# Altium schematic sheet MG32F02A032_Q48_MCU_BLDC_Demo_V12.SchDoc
size 307 x 215 mm
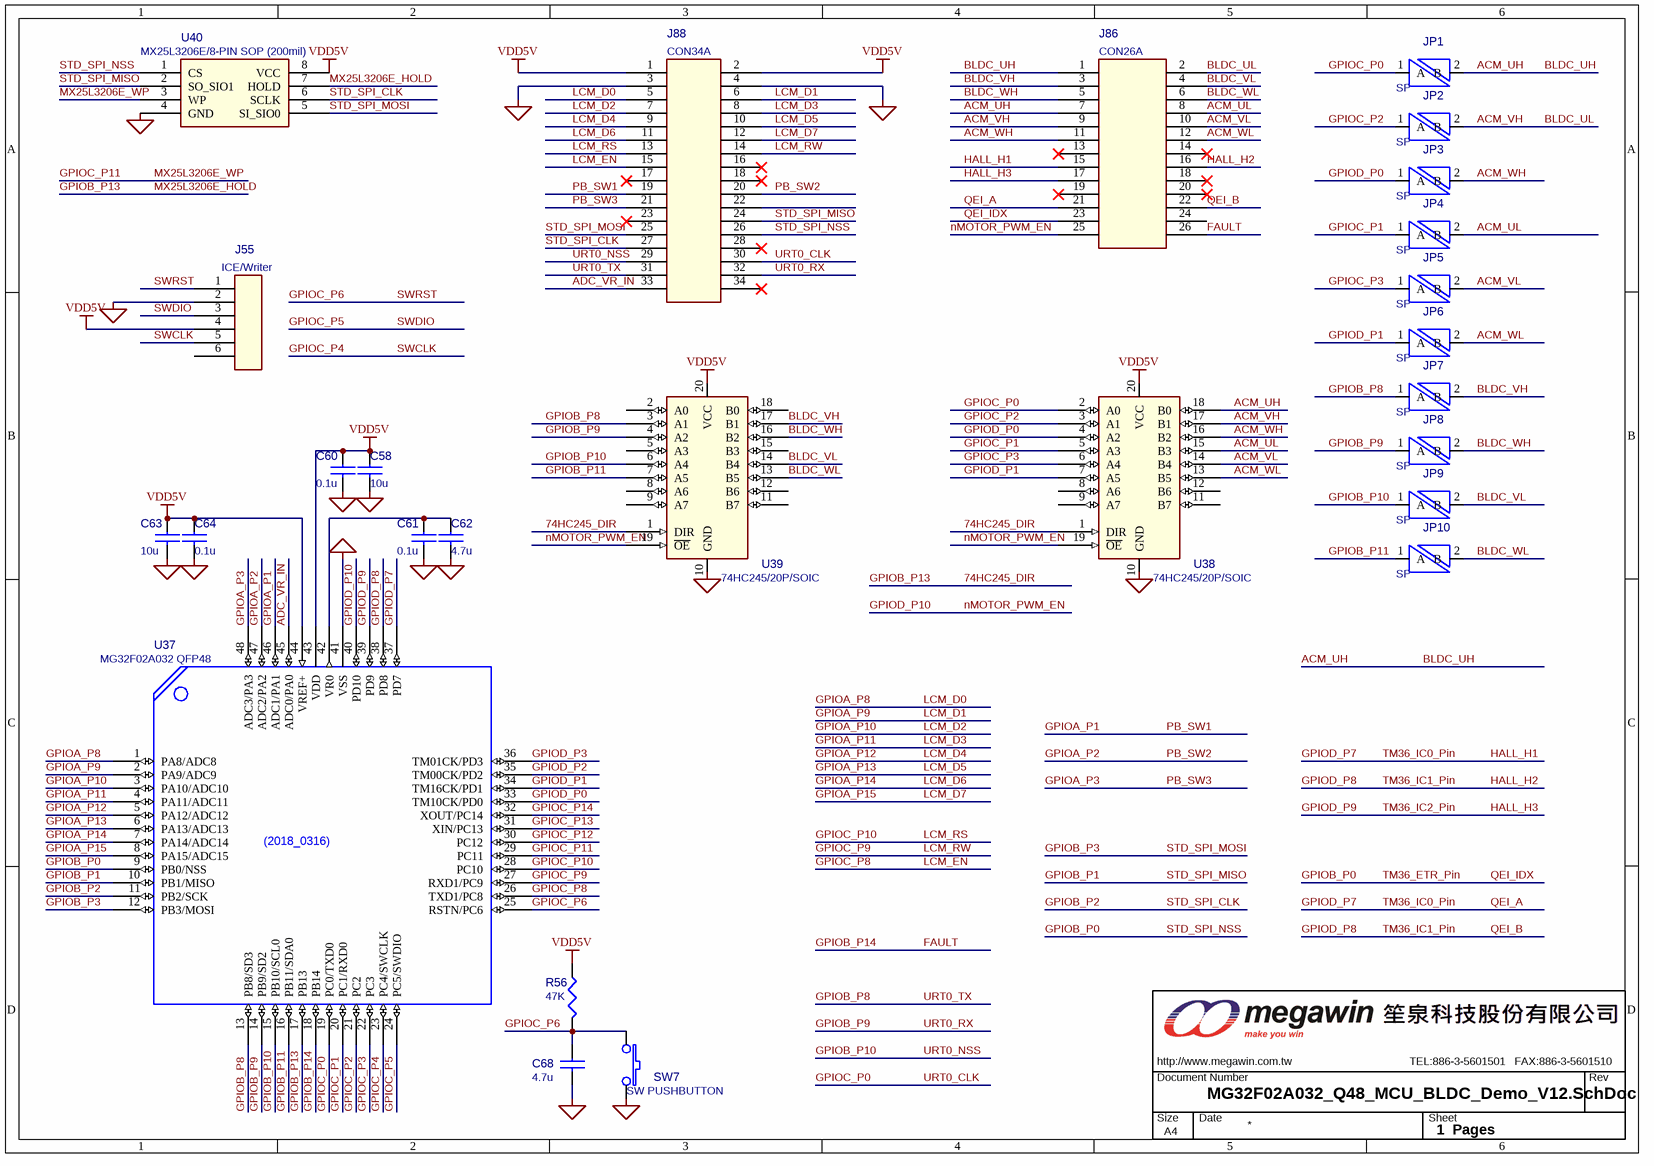
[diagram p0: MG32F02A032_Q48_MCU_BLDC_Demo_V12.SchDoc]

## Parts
C58  10u  [0805C]
C60  0.1u  [0805C]
C61  0.1u  [0805C]
C62  4.7u  [0805C]
C63  10u  [0805C]
C64  0.1u  [0805C]
C68  4.7u  [0805C]
J55  ICE/Writer  [PS6P254]
J86  CON26A  [PS13X2P254]
J88  CON34A  [PS17X2P254]
JP1  SP  [JUMP2C_SMD_1]
JP2  SP  [JUMP2C_SMD_1]
JP3  SP  [JUMP2C_SMD_1]
JP4  SP  [JUMP2C_SMD_1]
JP5  SP  [JUMP2C_SMD_1]
JP6  SP  [JUMP2C_SMD_1]
JP7  SP  [JUMP2C_SMD_1]
JP8  SP  [JUMP2C_SMD_1]
JP9  SP  [JUMP2C_SMD_1]
JP10  SP  [JUMP2C_SMD_1]
MW1  OrgAddr3: TEL:886-3-5601501   FAX:886-3-5601510  Page Size: A4  [MEGAWIN_3.4]  (hidden comment: MW-A4)  (no BOM)
R56  47K  [0805R]
SW7  SW PUSHBUTTON  [SW_T_2P]
U37  MG32F02A032 QFP48  [LQFP48_7X7_050]
U38  74HC245/20P/SOIC  [SO20_300P127]
U39  74HC245/20P/SOIC  [SO20_300P127]
U40  MX25L3206E/8-PIN SOP (200mil)  [SO8_208P127]

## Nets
GND: C58.2 C60.2 C61.2 C62.2 C63.2 C64.2 C68.2 J55.2 J88.3 J88.4 SW7.2 U37.41(VSS) U38.10(GND) U39.10(GND) U40.4(GND)
VDD5V: C58.1 C60.1 C63.1 C64.1 J55.4 J88.1 J88.2 R56.1 U37.43(VDD) U37.44(VREF+) U38.20(VCC) U39.20(VCC) U40.8(VCC)
74HC245_DIR: U37.17(PB13) U38.1(DIR) U39.1(DIR) U40.7(HOLD)  [also labelled GPIOB_P13, MX25L3206E_HOLD]
ACM_UH: J86.1 J86.7 JP1.2(B) U38.18(B0)  [also labelled BLDC_UH]
ACM_UL: J86.8 JP4.2(B) U38.15(B3)
ACM_VH: J86.2 J86.9 JP2.2(B) U38.17(B1)  [also labelled BLDC_UL]
ACM_VL: J86.10 JP5.2(B) U38.14(B4)
ACM_WH: J86.11 JP3.2(B) U38.16(B2)
ACM_WL: J86.12 JP6.2(B) U38.13(B5)
ADC_VR_IN: J88.33 U37.45(ADC0/PA0)
BLDC_VH: J86.3 JP7.2(B) U39.17(B1)
BLDC_VL: J86.4 JP9.2(B) U39.14(B4)
BLDC_WH: J86.5 JP8.2(B) U39.16(B2)
BLDC_WL: J86.6 JP10.2(B) U39.13(B5)
FAULT: J86.26 U37.18(PB14)  [also labelled GPIOB_P14]
GPIOA_P1: J88.19 U37.46(ADC1/PA1)  [also labelled PB_SW1]
GPIOA_P2: J88.20 U37.47(ADC2/PA2)  [also labelled PB_SW2]
GPIOA_P3: J88.21 U37.48(ADC3/PA3)  [also labelled PB_SW3]
GPIOA_P8: J88.5 U37.1(PA8/ADC8)  [also labelled LCM_D0]
GPIOA_P9: J88.6 U37.2(PA9/ADC9)  [also labelled LCM_D1]
GPIOA_P10: J88.7 U37.3(PA10/ADC10)  [also labelled LCM_D2]
GPIOA_P11: J88.8 U37.4(PA11/ADC11)  [also labelled LCM_D3]
GPIOA_P12: J88.9 U37.5(PA12/ADC12)  [also labelled LCM_D4]
GPIOA_P13: J88.10 U37.6(PA13/ADC13)  [also labelled LCM_D5]
GPIOA_P14: J88.11 U37.7(PA14/ADC14)  [also labelled LCM_D6]
GPIOA_P15: J88.12 U37.8(PA15/ADC15)  [also labelled LCM_D7]
GPIOB_P0: J86.23 J88.26 U37.9(PB0/NSS) U40.1(CS)  [also labelled QEI_IDX, STD_SPI_NSS, TM36_ETR_Pin]
GPIOB_P1: J88.24 U37.10(PB1/MISO) U40.2(SO_SIO1)  [also labelled STD_SPI_MISO]
GPIOB_P2: J88.27 U37.11(PB2/SCK) U40.6(SCLK)  [also labelled STD_SPI_CLK]
GPIOB_P3: J88.25 U37.12(PB3/MOSI) U40.5(SI_SIO0)  [also labelled STD_SPI_MOSI]
GPIOB_P8: J88.31 JP7.1(A) U37.13(PB8/SD3) U39.3(A1)  [also labelled URT0_TX]
GPIOB_P9: J88.32 JP8.1(A) U37.14(PB9/SD2) U39.4(A2)  [also labelled URT0_RX]
GPIOB_P10: J88.29 JP9.1(A) U37.15(PB10/SCL0) U39.6(A4)  [also labelled URT0_NSS]
GPIOB_P11: JP10.1(A) U37.16(PB11/SDA0) U39.7(A5)
GPIOC_P0: J88.30 JP1.1(A) U37.19(PC0/TXD0) U38.2(A0)  [also labelled URT0_CLK]
GPIOC_P1: JP4.1(A) U37.20(PC1/RXD0) U38.5(A3)
GPIOC_P2: JP2.1(A) U37.21(PC2) U38.3(A1)
GPIOC_P3: JP5.1(A) U37.22(PC3) U38.6(A4)
GPIOC_P4: J55.5 U37.23(PC4/SWCLK)  [also labelled SWCLK]
GPIOC_P5: J55.3 U37.24(PC5/SWDIO)  [also labelled SWDIO]
GPIOC_P6: C68.1 J55.1 R56.2 SW7.1 U37.25(RSTN/PC6)  [also labelled SWRST]
GPIOC_P8: J88.15 U37.26(TXD1/PC8)  [also labelled LCM_EN]
GPIOC_P9: J88.14 U37.27(RXD1/PC9)  [also labelled LCM_RW]
GPIOC_P10: J88.13 U37.28(PC10)  [also labelled LCM_RS]
GPIOC_P11: U37.29(PC11) U40.3(WP)  [also labelled MX25L3206E_WP]
GPIOC_P12: U37.30(PC12)
GPIOC_P13: U37.31(XIN/PC13)
GPIOC_P14: U37.32(XOUT/PC14)
GPIOD_P0: JP3.1(A) U37.33(TM10CK/PD0) U38.4(A2)
GPIOD_P1: JP6.1(A) U37.34(TM16CK/PD1) U38.7(A5)
GPIOD_P2: U37.35(TM00CK/PD2)
GPIOD_P3: U37.36(TM01CK/PD3)
GPIOD_P7: J86.15 J86.21 U37.37(PD7)  [also labelled HALL_H1, QEI_A, TM36_IC0_Pin]
GPIOD_P8: J86.16 J86.22 U37.38(PD8)  [also labelled HALL_H2, QEI_B, TM36_IC1_Pin]
GPIOD_P9: J86.17 U37.39(PD9)  [also labelled HALL_H3, TM36_IC2_Pin]
GPIOD_P10: J86.25 U37.40(PD10) U38.19(~{OE}) U39.19(~{OE})  [also labelled nMOTOR_PWM_EN]
NetC61_1: C61.1 C62.1 U37.42(VR0)

Not connected (* = marked no-connect by the designer): J55 6; J86 13* 14* 18* 19* 20* 24; J88 16* 17* 18* 22 23* 28* 34*; U38 8(A6) 9(A7) 11(B7) 12(B6); U39 2(A0) 5(A3) 8(A6) 9(A7) 11(B7) 12(B6) 15(B3) 18(B0)

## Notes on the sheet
- 1  Pages

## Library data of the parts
C58 C60-C64 C68 = CAP NP
J55 = CON6
MW1 = MW_A4_1
R56 = RESISTOR
U37 = IC-MG32F02A-LQFP48: SPLIT_INST: TRUE; SWAP_INFO: (S1+S2); OriginalSymbolOrigin: (0,0); Designator: A
U38 U39 = 74HC245_0
U40 = MX25L3206E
